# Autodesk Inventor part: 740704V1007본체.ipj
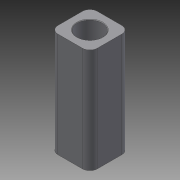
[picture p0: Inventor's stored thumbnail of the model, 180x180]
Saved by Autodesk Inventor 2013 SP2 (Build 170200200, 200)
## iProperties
Created: 2024-07
Part Number: 740704V1007본체.ipj
Material: Generic
Document SubType Name: Modeling
Designer: a
Density: 1 g/cm^3
Author: a
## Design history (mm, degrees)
sketch "스케치1"
  geometry: L1 (-25, 40)-(25, 40); L2 (40, 25)-(40, -25); L3 (25, -40)-(-25, -40); L4 (-40, -25)-(-40, 25); L5 (-40, 40)-(40, -40); L6 (40, 40)-(-40, -40); A1 r 15 centre (-25, 25) between (-25, 40) and (-40, 25); A2 r 15 centre (25, 25) between (40, 25) and (25, 40); A3 r 15 centre (-25, -25) between (-40, -25) and (-25, -40); A4 r 15 centre (25, -25) between (25, -40) and (40, -25); 1 further point
  constraints: 12 end point, 8 point on circle, 8 point on line, 8 tangent, 4 centre point, 3 equal radius, 2 midpoint, 2 parallel, 1 horizontal, 1 perpendicular
  dimensions: "d0" = 80 distance of L5.start L6.start; "d2" = 80 distance of L6.start L5.end; "d3" = 15 radius of A1
extrude "돌출1" new body sketch "스케치1" stored distance "d4" = 212; taper "d5" = 0 deg
sketch "스케치2"
  geometry: C1 r 20.5 at (0, 0); 1 further point
  constraints: 1 centre point, 1 coincident
  dimensions: "d6" = 41 diameter of C1
extrude "돌출2" cut sketch "스케치2" distance "d8" = 6; taper "d9" = 0 deg
sketch "스케치3"
  geometry: C1 r 32 at (0, 0); 5 further points
  constraints: 1 centre point, 1 coincident, 1 vertical alignment, 5 other
  dimensions: "d10" = 64 diameter of C1; "d12" = 31.5 distance of point (0, 0) point (0, 31.5); "d15" = 360 deg dimension on C1.centre point (0, 31.5) (derived)
hole "구멍1" sketch "스케치3" at (0, 31.5), (-31.5, 0), (0, -31.5), (31.5, 0) diameter "d17" = 3.242; stored, may be unused: countersink angle "d21" = 90 deg, drill point angle "d23" = 118 deg; dims "d18" = 12, "d19" = 4, "d20" = 2, "d22" = 14
sketch "스케치4"
  geometry: C1 r 25.5 at (0, 0); 1 further point
  constraints: 1 centre point, 1 coincident
  dimensions: "d24" = 51 diameter of C1
extrude "돌출3" cut sketch "스케치4" distance "d26" = 212; taper "d27" = 0 deg
chamfer "모따기1" distance "d28" = 1; stored, may be unused: second distance "d29" = 2, angle "d30" = 45 deg
sketch "스케치5"
  geometry: L1 (0, 212)-(50, 212) reference; 2 further points
  constraints: 1 vertical alignment, 1 other
  dimensions: "d31" = 90 distance from line of L1 point (25, 122)
feature "엠보싱1" sketch "스케치5" dims "d2" = 80, "d15" = 360 deg (derived), "d32" = 0.5, "d33" = 0
node "솔리드1"
